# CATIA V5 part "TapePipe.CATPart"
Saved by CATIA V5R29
Part number: TapePipe
Bounding box of the stored display mesh (mm): x -50 to 200, y -20 to 100, z -25 to 25
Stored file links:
  C:\Users\Administrator\Desktop\프로젝트\Boxfold\TapePipe.CATPart
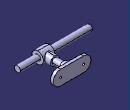
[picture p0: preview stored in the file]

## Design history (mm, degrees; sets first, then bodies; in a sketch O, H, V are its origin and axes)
Body1 (main body)
  Sketch1 on yz-plane, origin (0, 0, 0), H (0, 1, 0), V (0, 0, 1)
    circle A1 centre (0, 0) radius 10
    radius A1 = 10
  Pad1: profile Sketch1, direction (1, 0, 0), length 200, opposite side length 50
  Plane1: type Offset, RefPlane zx-plane, Offset 100
  Sketch2 on Plane1, origin (0, 100, 0), H (1, 0, 0), V (0, 0, 1)
    construction line L1 (70, 0) -> (150, 0)
    point P1 (70, 0)
    point P2 (150, 0)
    line L2 (70, 25) -> (150, 25)
    line L3 (150, -25) -> (70, -25)
    arc A1 centre (150, 0) radius 25 from (150, 25) to (150, -25) cw
    arc A2 centre (70, 0) radius 25 from (70, -25) to (70, 25) cw
    distance L2 L3 = 50
    length L1 = 80
    distance P2 O = 150
    coincidence: P1 H
    horizontal: L1 H
    tangency: A1 L2, A2 L2, A1 L3, A2 L3
  Pad2: profile Sketch2, direction (0, -1, 0), length 10
  Sketch3 on end face of Pad2, origin (0, 90, 0), H (1, 0, 0), V (0, 0, 1)
    circle A1 centre (110, 0) radius 15
    point P1 (110, 0)
    radius A1 = 15
    distance P1 V = 110
    coincidence: P1 H
  Pad3: profile Sketch3, direction (0, -1, 0), length 20
  Sketch4 on end face of Pad3, origin (0, 70, 0), H (1, 0, 0), V (0, 0, 1)
    circle A1 centre (110, 0) radius 10
    reference projected circle E1 centre (110, 0) radius 15 from edge [face of Pad3 from Sketch3.A1 | end face of Pad3]
    radius A1 = 10
    concentricity: A1 E1
  Pocket1: profile Sketch4, direction (0, 1, 0), up to end face of Pad2
  Sketch5 on end face of Pocket1, origin (0, 90, 0), H (1, 0, 0), V (0, 0, 1)
    circle A1 centre (110, 0) radius 10
    reference projected circle E1 centre (110, 0) radius 10 from edge [end face of Pad3 | face of Pocket1 from Sketch4.A1]
    coincidence: A1 E1
  Pad4: profile Sketch5, direction (0, -1, 0), length 70
  Plane2: type Offset, RefPlane yz-plane, Offset 110
  Sketch6 on Plane2, origin (110, 0, 0), H (0, 0, 1), V (0, -1, 0)
    circle A1 centre (0, 0) radius 20
    circle A2 centre (0, 0) radius 10
    reference projected circle E1 centre (0, 0) radius 10 from edge [face of Pad1 from Sketch1.A1 | end face of Pad1]
    radius A1 = 20
    coincidence: A2 E1
  Pad5: profile Sketch6, direction (1, 0, 0), length 20, mirrored extent
  Sketch7 on Plane2, origin (110, 0, 0), H (0, 0, -1), V (0, 1, 0)
    line L1 (-10, 40) -> (-10, 10)
    line L2 (-10, 10) -> (-15, 10)
    line L3 (-15, 10) -> (-15, 40)
    line L4 (-15, 40) -> (-10, 40)
    distance L3 L1 = 5
    distance L1 V = 10
    distance L4 L2 = 30
    distance L2 H = 10
    vertical: L1 V, L3 V
    horizontal: L2 H, L4 H
  Sketch8 on Plane2, origin (110, 0, 0), H (0, 1, 0), V (0, 0, 1)
    line L1 (-7.6889, 0) -> (48.0557, 0)
    point P1 (-7.6889, 0)
    coincidence: P1 H
    horizontal: L1 H
  Shaft1: profile Sketch7, axis axis of face of Pad4 from Sketch5.A1, angle 360
  Sketch9 on end face of Pad2, origin (164.5922, 90, -7.9579), H (1, 0, 0), V (0, 0, 1)
    point P1 (-14.5922, 7.9579)
    reference projected arc E1 centre (-14.5922, 7.9579) radius 25 from (-14.5922, -17.0421) to (-14.5922, 32.9579) ccw from edge [face of Pad2 from Sketch2.A1 | end face of Pad2]
    concentricity: P1 E1
  Hole1: placed by Sketch9, at (150, 90, 0) direction (0, 1, 0), diameter 6.6, through (limit type 6), counterbore diameter 15, counterbore depth 0.5
  Mirror1: of Hole1, about Plane2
